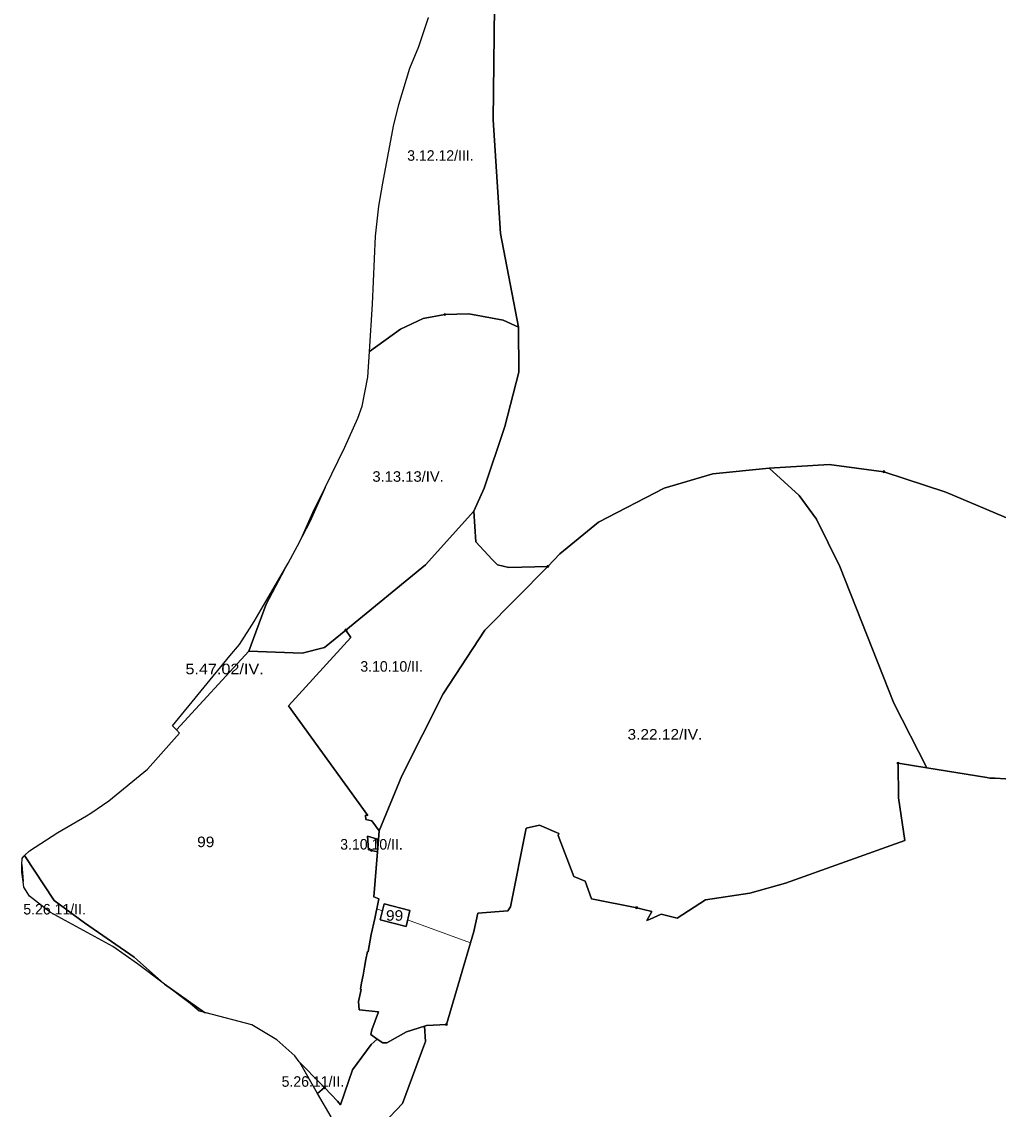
# Model space of a CAD drawing. Extents: x -650455 to -642254, y -1075222 to -1066610.
# Drawn here: x -649075 to -648146, y -1074176 to -1073142 of the extents above; entities that cross this region are included whole.
import ezdxf
from ezdxf.enums import TextEntityAlignment as Align

# ---------------------------------------------------------------- set-up
doc = ezdxf.new("R2010")
doc.units = 0
doc.header["$LTSCALE"] = 4
doc.header["$PDMODE"] = 32
doc.header["$PDSIZE"] = 2
for name, color, linetype, lineweight in [('1', 7, 'Continuous', 25), ('12', 7, 'Continuous', 13), ('13', 7, 'Continuous', 13), ('14', 7, 'Continuous', 13)]:
    doc.layers.add(name, color=color, linetype=linetype, lineweight=lineweight)
doc.layers.add('2', color=7, linetype='Continuous')

msp = doc.modelspace()

# ---------------------------------------------------------------- linework, layer by layer
at = {"layer": '1'}
for points in [[(-648625, -1073100.5), (-648626.5, -1073235.5), (-648619.5, -1073343.5), (-648602.5, -1073432.5), (-648617, -1073426), (-648649.5, -1073420.001), (-648672.5, -1073420.5), (-648693, -1073424.5), (-648714.5, -1073434.501), (-648744.217, -1073455.79), (-648741.42, -1073410.767), (-648738.549, -1073346.144), (-648735.389, -1073317.422), (-648731.52, -1073295.605), (-648721.316, -1073241.598), (-648716.146, -1073220.918), (-648705.806, -1073186.453), (-648697.333, -1073165.774), (-648687.999, -1073138.202)], [(-648602, -1073475.501), (-648602.5, -1073432.5), (-648619.5, -1073343.5), (-648626.5, -1073235.5), (-648625, -1073100.5)], [(-648062.5, -1073646.001), (-648196, -1073589.501), (-648255, -1073570), (-648307, -1073563), (-648364, -1073566.5), (-648417.5, -1073572), (-648464, -1073585.501), (-648526.5, -1073618.001), (-648563, -1073648), (-648574.5, -1073660), (-648611.5, -1073661), (-648622.5, -1073658.501), (-648627.5, -1073653.501), (-648643, -1073636.5), (-648645, -1073607.5), (-648635, -1073585.501), (-648615.5, -1073527), (-648602, -1073475.501)], [(-648752.57, -1074061.851), (-648751.57, -1074055.821), (-648750.22, -1074048.451), (-648748.85, -1074041.09), (-648747.5, -1074033.741), (-648746.05, -1074026.171), (-648745.45, -1074026.31), (-648745.41, -1074026.111), (-648742.61, -1074010.011), (-648739.19, -1073994.71), (-648735.92, -1073979.321), (-648735.23, -1073976.071), (-648740, -1073974.001), (-648736.58, -1073931.24), (-648736.321, -1073928.012), (-648735, -1073911.5), (-648713.5, -1073859), (-648674, -1073781), (-648634.5, -1073720.5), (-648574.5, -1073660), (-648563, -1073648), (-648526.5, -1073618.001), (-648464, -1073585.501), (-648417.5, -1073572), (-648364, -1073566.5), (-648335.5, -1073592.501), (-648319, -1073615), (-648297, -1073660), (-648245.5, -1073790), (-648214, -1073851.501)], [(-648110, -1073864.001), (-648149.105, -1073861.45), (-648149.15, -1073861.451), (-648154.13, -1073861.481), (-648157.04, -1073860.831), (-648214, -1073851.501), (-648245.5, -1073790), (-648297, -1073660), (-648319, -1073615), (-648335.5, -1073592.501), (-648364, -1073566.5), (-648307, -1073563), (-648255, -1073570), (-648196, -1073589.501), (-648062.5, -1073646.001)], [(-648901, -1074084.001), (-648939, -1074057), (-648968, -1074031.501), (-649015, -1073999.001), (-649044, -1073977.501), (-649072.294, -1073934.835), (-649067.407, -1073930.333), (-649040.497, -1073913.053), (-649013.146, -1073897.066), (-649009.16, -1073894.737), (-648991.907, -1073882.759), (-648955.288, -1073852.817), (-648924.795, -1073818.448), (-648927.621, -1073815.481), (-648859, -1073740.5), (-648808, -1073742.501), (-648787, -1073737), (-648766.5, -1073720.5), (-648762, -1073727.501), (-648821, -1073792.501), (-648745.64, -1073896.781), (-648747.8, -1073896.441), (-648747.45, -1073900.56), (-648741.97, -1073901.861), (-648735, -1073911.5)], [(-648214, -1073851.501), (-648241.5, -1073847), (-648241, -1073880.001), (-648235, -1073920.501), (-648348.5, -1073961.001), (-648382.5, -1073970.501), (-648424.5, -1073977.001), (-648451.5, -1073994.501), (-648466.848, -1073990.514), (-648477.31, -1073995.351), (-648480.31, -1073996.631), (-648478.94, -1073993.79), (-648475.77, -1073988.2), (-648483.64, -1073986.15), (-648490, -1073984.5), (-648533, -1073976), (-648539.18, -1073959.08), (-648549.76, -1073954.86), (-648564.75, -1073915.911), (-648564.13, -1073914.061), (-648582.5, -1073906.001), (-648595, -1073909.001), (-648610, -1073983.5), (-648612.5, -1073987.5), (-648641, -1073989.501), (-648644.975, -1074007.201), (-648671, -1074095.501), (-648690, -1074096.5), (-648691.81, -1074097.071), (-648709, -1074102.501), (-648727.5, -1074113), (-648731.5, -1074113), (-648736.831, -1074109.292), (-648743, -1074105), (-648742, -1074100.5), (-648735.5, -1074083.501), (-648754, -1074081.5), (-648754.5, -1074073.5), (-648752.09, -1074062.33), (-648752.57, -1074061.851)], [(-648690.92, -1074111.641), (-648691.81, -1074097.071), (-648690, -1074096.5), (-648671, -1074095.501), (-648644.975, -1074007.201), (-648641, -1073989.501), (-648612.5, -1073987.5), (-648610, -1073983.5), (-648595, -1073909.001), (-648582.5, -1073906.001), (-648564.13, -1073914.061), (-648564.75, -1073915.911), (-648549.76, -1073954.86), (-648539.18, -1073959.08), (-648533, -1073976), (-648490, -1073984.5), (-648483.64, -1073986.15), (-648475.77, -1073988.2), (-648478.94, -1073993.79), (-648480.31, -1073996.631), (-648477.31, -1073995.351), (-648466.848, -1073990.514), (-648451.5, -1073994.501), (-648424.5, -1073977.001), (-648382.5, -1073970.501), (-648348.5, -1073961.001), (-648235, -1073920.501), (-648241, -1073880.001), (-648241.5, -1073847), (-648214, -1073851.501), (-648157.04, -1073860.831), (-648154.13, -1073861.481), (-648149.15, -1073861.451), (-648149.105, -1073861.45), (-648110, -1073864.001)], [(-648735, -1073911.5), (-648736.321, -1073928.012), (-648736.6, -1073919.261), (-648746.08, -1073916.36), (-648744.97, -1073929.301), (-648742.17, -1073929.951), (-648736.58, -1073931.24), (-648740, -1073974.001), (-648735.23, -1073976.071), (-648735.92, -1073979.321), (-648739.19, -1073994.71), (-648742.61, -1074010.011), (-648745.41, -1074026.111), (-648745.45, -1074026.31), (-648746.05, -1074026.171), (-648747.5, -1074033.741), (-648748.85, -1074041.09), (-648750.22, -1074048.451), (-648751.57, -1074055.821), (-648752.57, -1074061.851), (-648752.09, -1074062.33), (-648754.5, -1074073.5), (-648754, -1074081.5), (-648735.5, -1074083.501), (-648742, -1074100.5), (-648743, -1074105), (-648736.831, -1074109.292), (-648742.6, -1074114.47), (-648760.17, -1074138.5), (-648771.8, -1074172.011), (-648774.5, -1074168.501), (-648787, -1074155.501), (-648790.527, -1074151.91), (-648810.451, -1074131.626), (-648810.9, -1074130.849), (-648815.201, -1074125.143), (-648832.102, -1074109.996), (-648856.045, -1074095.905), (-648899.457, -1074084.507), (-648901, -1074084.001)], [(-648780.692, -1074183.167), (-648793.41, -1074161.141), (-648787, -1074155.501), (-648774.5, -1074168.501), (-648771.8, -1074172.011), (-648760.17, -1074138.5), (-648742.6, -1074114.47), (-648736.831, -1074109.292), (-648731.5, -1074113), (-648727.5, -1074113), (-648709, -1074102.501), (-648691.81, -1074097.071), (-648690.92, -1074111.641), (-648693.71, -1074119.171), (-648712.77, -1074170.511), (-648730.34, -1074189.22)], [(-648730.34, -1074189.22), (-648712.77, -1074170.511), (-648693.71, -1074119.171), (-648690.92, -1074111.641)]]:
    msp.add_lwpolyline(points, dxfattribs=at)
for points in [[(-648602.5, -1073432.5), (-648602, -1073475.501), (-648615.5, -1073527), (-648635, -1073585.501), (-648645, -1073607.5), (-648691, -1073658.501), (-648766.5, -1073720.5), (-648787, -1073737), (-648808, -1073742.501), (-648859, -1073740.5), (-648842.5, -1073696), (-648824.895, -1073662.886), (-648821.41, -1073656.907), (-648810.352, -1073636.229), (-648808.214, -1073631.51), (-648800.5, -1073617.001), (-648786.307, -1073585.006), (-648767.557, -1073546.618), (-648755.207, -1073519.046), (-648751.042, -1073507.7), (-648745.729, -1073480.128), (-648744.217, -1073455.79), (-648714.5, -1073434.501), (-648693, -1073424.5), (-648672.5, -1073420.5), (-648649.5, -1073420.001), (-648617, -1073426)], [(-648800.5, -1073617.001), (-648808.214, -1073631.51), (-648797.858, -1073608.656), (-648786.307, -1073585.006)], [(-648574.5, -1073660), (-648634.5, -1073720.5), (-648674, -1073781), (-648713.5, -1073859), (-648735, -1073911.5), (-648741.97, -1073901.861), (-648747.45, -1073900.56), (-648747.8, -1073896.441), (-648745.64, -1073896.781), (-648821, -1073792.501), (-648762, -1073727.501), (-648766.5, -1073720.5), (-648691, -1073658.501), (-648645, -1073607.5), (-648643, -1073636.5), (-648627.5, -1073653.501), (-648622.5, -1073658.501), (-648611.5, -1073661)], [(-648859, -1073740.5), (-648927.621, -1073815.481), (-648931.394, -1073811.522), (-648876.987, -1073745.13), (-648867.83, -1073734.107), (-648853.721, -1073712.339), (-648824.895, -1073662.886), (-648842.5, -1073696)], [(-648736.321, -1073928.012), (-648736.58, -1073931.24), (-648742.17, -1073929.951), (-648744.97, -1073929.301), (-648746.08, -1073916.36), (-648736.6, -1073919.261)], [(-648901, -1074084.001), (-648899.457, -1074084.507), (-648905.982, -1074082.794), (-648914.505, -1074075.443), (-648964.729, -1074037.751), (-648988.179, -1074021.285), (-649047.332, -1073988.878), (-649067.402, -1073973.379), (-649072.684, -1073964.925), (-649073.486, -1073959.574), (-649074.593, -1073943.317), (-649074.444, -1073937.802), (-649072.864, -1073935.36), (-649072.294, -1073934.835), (-649044, -1073977.501), (-649015, -1073999.001), (-648968, -1074031.501), (-648939, -1074057)], [(-649074.593, -1073943.317), (-649073.486, -1073959.574), (-649074.797, -1073950.834)], [(-648705.68, -1073987.171), (-648709.33, -1074002.301), (-648734.08, -1073996.051), (-648730.17, -1073980.81)], [(-648705.68, -1073987.171), (-648730.17, -1073980.81), (-648734.08, -1073996.051), (-648709.33, -1074002.301)], [(-648787, -1074155.501), (-648793.41, -1074161.141), (-648810.451, -1074131.626), (-648790.527, -1074151.91)]]:
    msp.add_lwpolyline(points, close=True, dxfattribs=at)
at = {"layer": '12'}
msp.add_line((-648793.41, -1074161.141), (-648787, -1074155.501), dxfattribs=at)
for points in [[(-648741.97, -1073901.861), (-648735, -1073911.5), (-648713.5, -1073859), (-648674, -1073781), (-648634.5, -1073720.5), (-648574.5, -1073660), (-648611.5, -1073661), (-648622.5, -1073658.501), (-648627.5, -1073653.501), (-648643, -1073636.5), (-648645, -1073607.5), (-648691, -1073658.501), (-648766.5, -1073720.5), (-648762, -1073727.501), (-648821, -1073792.501), (-648745.64, -1073896.781), (-648747.8, -1073896.441), (-648747.45, -1073900.56)], [(-648742.17, -1073929.951), (-648736.58, -1073931.24), (-648736.321, -1073928.012), (-648736.6, -1073919.261), (-648746.08, -1073916.36), (-648744.97, -1073929.301)], [(-649047.332, -1073988.878), (-648988.179, -1074021.285), (-648964.729, -1074037.751), (-648914.505, -1074075.443), (-648905.982, -1074082.794), (-648899.457, -1074084.507), (-648901, -1074084.001), (-648939, -1074057), (-648968, -1074031.501), (-649015, -1073999.001), (-649044, -1073977.501), (-649072.294, -1073934.835), (-649072.864, -1073935.36), (-649074.444, -1073937.802), (-649074.593, -1073943.317), (-649073.486, -1073959.574), (-649072.684, -1073964.925), (-649067.402, -1073973.379)]]:
    msp.add_lwpolyline(points, close=True, dxfattribs=at)
for points in [[(-648730.34, -1074189.22), (-648712.77, -1074170.511), (-648693.71, -1074119.171), (-648690.92, -1074111.641), (-648691.81, -1074097.071), (-648709, -1074102.501), (-648727.5, -1074113), (-648731.5, -1074113), (-648736.831, -1074109.292), (-648742.6, -1074114.47), (-648760.17, -1074138.5), (-648771.8, -1074172.011), (-648774.5, -1074168.501), (-648787, -1074155.501), (-648793.41, -1074161.141), (-648780.692, -1074183.167)], [(-648787, -1074155.501), (-648790.527, -1074151.91), (-648810.451, -1074131.626), (-648793.41, -1074161.141)]]:
    msp.add_lwpolyline(points, dxfattribs=at)
for p in [(-648742.17, -1073929.951), (-648787, -1074155.501)]:
    msp.add_point(p, dxfattribs=at)
at = {"layer": '13'}
for points in [[(-648687.999, -1073138.202), (-648697.333, -1073165.774), (-648705.806, -1073186.453), (-648716.146, -1073220.918), (-648721.316, -1073241.598), (-648731.52, -1073295.605), (-648735.389, -1073317.422), (-648738.549, -1073346.144), (-648741.42, -1073410.767), (-648744.217, -1073455.79), (-648714.5, -1073434.501), (-648693, -1073424.5), (-648672.5, -1073420.5), (-648649.5, -1073420.001), (-648617, -1073426), (-648602.5, -1073432.5), (-648619.5, -1073343.5), (-648626.5, -1073235.5), (-648625, -1073100.5)], [(-648625, -1073100.5), (-648626.5, -1073235.5), (-648619.5, -1073343.5), (-648602.5, -1073432.5), (-648602, -1073475.501), (-648615.5, -1073527), (-648635, -1073585.501), (-648645, -1073607.5), (-648643, -1073636.5), (-648627.5, -1073653.501), (-648622.5, -1073658.501), (-648611.5, -1073661), (-648574.5, -1073660)], [(-648574.5, -1073660), (-648563, -1073648), (-648526.5, -1073618.001), (-648464, -1073585.501), (-648417.5, -1073572), (-648364, -1073566.5), (-648307, -1073563), (-648255, -1073570)], [(-648062.5, -1073646.001), (-648196, -1073589.501), (-648255, -1073570), (-648307, -1073563), (-648364, -1073566.5), (-648335.5, -1073592.501), (-648319, -1073615), (-648297, -1073660), (-648245.5, -1073790), (-648214, -1073851.501), (-648157.04, -1073860.831), (-648154.13, -1073861.481), (-648149.15, -1073861.451), (-648149.105, -1073861.45), (-648110, -1073864.001)], [(-648255, -1073570), (-648196, -1073589.501), (-648062.5, -1073646.001), (-647997.5, -1073679.5), (-647977, -1073687.001), (-647941, -1073695.001), (-647920, -1073695.5), (-647891.5, -1073692.5), (-647875, -1073690.501), (-647823.5, -1073666.001), (-647745, -1073642.501), (-647710, -1073641.001), (-647684, -1073648), (-647654.5, -1073672), (-647648.56, -1073674.85), (-647570, -1073712.5), (-647585, -1073748.5)]]:
    msp.add_lwpolyline(points, dxfattribs=at)
for p in [(-648672.5, -1073420.5), (-648255, -1073570), (-648574.5, -1073660)]:
    msp.add_point(p, dxfattribs=at)
at = {"layer": '14'}
for points in [[(-648766.5, -1073720.5), (-648691, -1073658.501), (-648645, -1073607.5), (-648635, -1073585.501), (-648615.5, -1073527), (-648602, -1073475.501), (-648602.5, -1073432.5), (-648617, -1073426), (-648649.5, -1073420.001), (-648672.5, -1073420.5), (-648693, -1073424.5), (-648714.5, -1073434.501), (-648744.217, -1073455.79), (-648745.729, -1073480.128), (-648751.042, -1073507.7), (-648755.207, -1073519.046), (-648767.557, -1073546.618), (-648786.307, -1073585.006), (-648800.5, -1073617.001), (-648808.214, -1073631.51), (-648810.352, -1073636.229), (-648821.41, -1073656.907), (-648824.895, -1073662.886), (-648842.5, -1073696), (-648859, -1073740.5), (-648808, -1073742.501), (-648787, -1073737)], [(-648859, -1073740.5), (-648842.5, -1073696), (-648824.895, -1073662.886), (-648853.721, -1073712.339), (-648867.83, -1073734.107), (-648876.987, -1073745.13), (-648931.394, -1073811.522), (-648927.621, -1073815.481)]]:
    msp.add_lwpolyline(points, close=True, dxfattribs=at)
for points in [[(-648241.5, -1073847), (-648214, -1073851.501), (-648245.5, -1073790), (-648297, -1073660), (-648319, -1073615), (-648335.5, -1073592.501), (-648364, -1073566.5), (-648417.5, -1073572), (-648464, -1073585.501), (-648526.5, -1073618.001), (-648563, -1073648), (-648574.5, -1073660), (-648634.5, -1073720.5), (-648674, -1073781), (-648713.5, -1073859), (-648735, -1073911.5), (-648736.321, -1073928.012), (-648736.58, -1073931.24), (-648740, -1073974.001), (-648735.23, -1073976.071), (-648735.92, -1073979.321), (-648737.229, -1073985.48), (-648731.866, -1073987.422), (-648730.17, -1073980.81), (-648705.68, -1073987.171)], [(-648490, -1073984.5), (-648483.64, -1073986.15), (-648475.77, -1073988.2), (-648478.94, -1073993.79), (-648480.31, -1073996.631), (-648477.31, -1073995.351), (-648466.848, -1073990.514), (-648451.5, -1073994.501), (-648424.5, -1073977.001), (-648382.5, -1073970.501), (-648348.5, -1073961.001), (-648235, -1073920.501), (-648241, -1073880.001), (-648241.5, -1073847)], [(-648705.68, -1073987.171), (-648707.84, -1073996.123), (-648648.087, -1074017.761), (-648644.975, -1074007.201), (-648641, -1073989.501), (-648612.5, -1073987.5), (-648610, -1073983.5), (-648595, -1073909.001), (-648582.5, -1073906.001), (-648564.13, -1073914.061), (-648564.75, -1073915.911), (-648549.76, -1073954.86), (-648539.18, -1073959.08), (-648533, -1073976), (-648490, -1073984.5)], [(-648671, -1074095.501), (-648648.087, -1074017.761), (-648707.84, -1073996.123), (-648709.33, -1074002.301), (-648734.08, -1073996.051), (-648731.866, -1073987.422), (-648737.229, -1073985.48), (-648739.19, -1073994.71), (-648742.61, -1074010.011), (-648745.41, -1074026.111), (-648745.45, -1074026.31), (-648746.05, -1074026.171), (-648747.5, -1074033.741), (-648748.85, -1074041.09), (-648750.22, -1074048.451), (-648751.57, -1074055.821), (-648752.57, -1074061.851), (-648752.09, -1074062.33), (-648754.5, -1074073.5), (-648754, -1074081.5), (-648735.5, -1074083.501), (-648742, -1074100.5), (-648743, -1074105), (-648736.831, -1074109.292), (-648731.5, -1074113), (-648727.5, -1074113), (-648709, -1074102.501), (-648691.81, -1074097.071)], [(-648691.81, -1074097.071), (-648690, -1074096.5), (-648671, -1074095.501)]]:
    msp.add_lwpolyline(points, dxfattribs=at)
for p in [(-648766.5, -1073720.5), (-648241.5, -1073847), (-648490, -1073984.5), (-648671, -1074095.501)]:
    msp.add_point(p, dxfattribs=at)

# ---------------------------------------------------------------- texts
at = {"layer": '2'}
for s, p in [('3.12.12/III.', (-648676.665, -1073274.395)), ('3.10.10/II.', (-648723.083, -1073760.098)), ('3.10.10/II.', (-648742.201, -1073929.202)), ('5.26.11/II.', (-649043.547, -1073990.91)), ('5.26.11/II.', (-648797.931, -1074154.685))]:
    msp.add_text(s, height=10, dxfattribs=at).set_placement(p, align=Align.CENTER)
for s, width, p in [('3.13.13/IV.', 1.05, (-648707.405, -1073579.546)), ('5.47.02/IV.', 1.15, (-648881.907, -1073762.501)), ('3.22.12/IV.', 1.1, (-648463.217, -1073824.682)), ('99', 1.1, (-648899.843, -1073926.88)), ('99', 1.1, (-648720.26, -1073996.851))]:
    msp.add_text(s, height=10, dxfattribs=dict(at, width=width)).set_placement(p, align=Align.CENTER)

doc.saveas('drawing.dxf')
